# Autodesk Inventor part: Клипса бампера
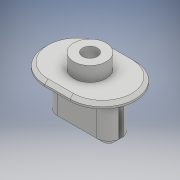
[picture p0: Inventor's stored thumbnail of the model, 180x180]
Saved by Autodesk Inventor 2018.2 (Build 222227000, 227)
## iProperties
Created: 2019-11
Part Number: Клипса бампера
Material: Типовые
Document SubType Name: Modeling
Designer: Administrator
Density: 1 g/cm^3
Appearance: По умолчанию
Author: Administrator
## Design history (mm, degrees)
sketch "Эскиз1"
  geometry: L1 (-10.704, 0)-(17.066, 0); L2 (-0.704, -10)-(7.066, -10); L3 (7.066, 10)-(-0.704, 10); A1 r 10 centre (-0.704, 0) between (-0.704, 10) and (-0.704, -10); A2 r 10 centre (7.066, 0) between (7.066, -10) and (7.066, 10); 2 further points
  constraints: 8 end point, 6 point on circle, 4 tangent, 2 centre point, 2 point on line, 1 horizontal, 1 midpoint, 1 parallel
  dimensions: "d0" = 27.77 distance of L1.start L1.end; "d1" = 20 diameter of A2
extrude "Выдавливание1" new body sketch "Эскиз1" distance "d2" = 1.6; taper "d3" = 0 deg
sketch "Эскиз2"
  geometry: C1 r 4.995 at (3.176, 0); A1 r 10 centre (-0.704, 0) between (-0.704, 10) and (-0.704, -10) reference; 1 further point
  constraints: 1 centre point
  dimensions: "d5" = 9.99 diameter of C1
extrude "Выдавливание2" join sketch "Эскиз2" distance "d6" = 4.5; taper "d7" = 0 deg
sketch "Эскиз3"
  geometry: C1 r 2.3 at (0, 0); 1 further point
  constraints: 1 centre point
  dimensions: "d8" = 4.6 diameter of C1
extrude "Выдавливание3" cut sketch "Эскиз3" distance "d9" = 5.3; taper "d10" = 0 deg
sketch "Эскиз4"
  geometry: L1 (-8.981, 0)-(3.019, 0); L2 (-8.981, -3.8)-(3.019, -3.8); L3 (3.019, 3.8)-(-8.981, 3.8); A1 r 3.8 centre (-8.981, 0) between (-8.981, 3.8) and (-8.981, -3.8); A2 r 3.8 centre (3.019, 0) between (3.019, -3.8) and (3.019, 3.8); 2 further points
  constraints: 8 end point, 4 point on circle, 4 tangent, 2 centre point, 1 horizontal, 1 midpoint, 1 parallel
  dimensions: "d12" = 6 distance of point (-2.981, 0) L1.end; "d13" = 7.6 diameter of A2
extrude "Выдавливание4" join sketch "Эскиз4" distance "d14" = 14; taper "d15" = 0 deg
sketch "Эскиз5"
  geometry: L1 (18.188, -0.71)-(-18.188, -0.71); L2 (-18.188, -0.71)-(-18.188, 0.71); L3 (-18.188, 0.71)-(18.188, 0.71); L4 (18.188, 0.71)-(18.188, -0.71); L5 (18.188, -0.71)-(-18.188, 0.71); L6 (-18.188, -0.71)-(18.188, 0.71); 1 further point
  constraints: 12 end point, 2 midpoint, 2 parallel, 1 horizontal, 1 perpendicular
extrude "Выдавливание5" cut sketch "Эскиз5" distance "d16" = 14; taper "d17" = 0 deg
chamfer "Фаска1" distance "d18" = 2; stored, may be unused: second distance "d19" = 2, angle "d20" = 45 deg
chamfer "Фаска2" distance "d21" = 2; stored, may be unused: second distance "d22" = 2, angle "d23" = 45 deg
chamfer "Фаска3" distance "d24" = 1; stored, may be unused: second distance "d25" = 2, angle "d26" = 45 deg
sketch "Эскиз6"
  geometry: C1 r 1.25 at (0, 0); 1 further point
  constraints: 1 centre point
  dimensions: "d27" = 2.5 diameter of C1
extrude "Выдавливание6" cut sketch "Эскиз6" distance "d28" = 15; taper "d29" = 0 deg
node "Твердое тело1"
